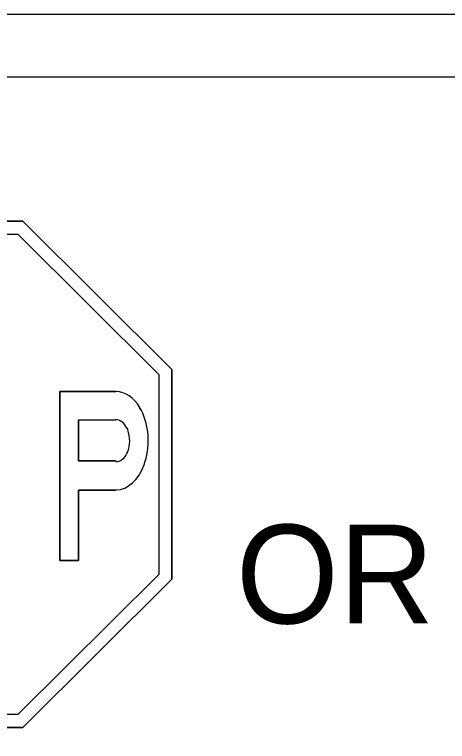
# Model space of a CAD drawing. Extents: x 21.7 to 29.1, y 5.9 to 16.2.
# Drawn here: x 28.039 to 28.39, y 13.558 to 14.147 of the extents above; entities that cross this region are included whole.
import ezdxf

# ---------------------------------------------------------------- set-up
doc = ezdxf.new("R2010")
doc.units = 0
for name, color, linetype in [('DETL-LINE', 7, 'Continuous'), ('DETL-NOTE', 7, 'Continuous'), ('USER-BORD', 7, 'Continuous')]:
    doc.layers.add(name, color=color, linetype=linetype)

msp = doc.modelspace()

# ---------------------------------------------------------------- linework, layer by layer
at = {"layer": 'DETL-LINE'}
for p, q in [((28.04574, 13.97933), (27.87647, 13.97933)), ((28.16646, 13.85926), (28.04574, 13.97933)), ((27.88041, 13.96883), (28.04181, 13.96883)), ((28.04181, 13.96883), (28.15597, 13.85532)), ((28.16646, 13.68933), (28.16646, 13.85926)), ((28.15597, 13.85532), (28.15597, 13.69327)), ((28.09101, 13.84155), (28.07592, 13.84155)), ((28.07592, 13.84155), (28.07592, 13.70442)), ((28.12119, 13.84155), (28.09101, 13.84155)), ((28.14088, 13.82711), (28.14022, 13.82842)), ((28.1418, 13.82612), (28.14116, 13.82727)), ((28.09101, 13.78512), (28.09101, 13.81858)), ((28.09101, 13.81858), (28.12119, 13.81858)), ((28.12119, 13.81858), (28.12147, 13.81861)), ((28.13038, 13.81202), (28.13038, 13.81137)), ((28.13018, 13.81167), (28.1308, 13.81027)), ((28.13038, 13.79186), (28.12948, 13.79008)), ((28.13038, 13.79168), (28.13038, 13.79186)), ((28.14405, 13.78205), (28.14501, 13.78492)), ((28.09101, 13.70442), (28.09101, 13.7615)), ((28.09101, 13.7615), (28.12119, 13.7615)), ((28.07592, 13.70442), (28.09101, 13.70442)), ((28.15597, 13.69327), (28.04181, 13.57976)), ((28.04574, 13.56926), (28.16646, 13.68933)), ((28.04181, 13.57976), (27.88041, 13.57976)), ((27.87647, 13.56926), (28.04574, 13.56926))]:
    msp.add_line(p, q, dxfattribs=at)
for points in [[(28.97321, 14.14685), (25.80407, 14.14685), (25.80407, 13.01694), (28.97321, 13.01694)], [(27.69786, 14.09638), (28.91887, 14.09638), (28.91887, 13.07685), (27.69786, 13.07685)]]:
    msp.add_lwpolyline(points, close=True, dxfattribs=at)
for points in [[(28.12147, 13.84137), (28.12119, 13.84155)], [(28.14022, 13.82842), (28.1405, 13.82843)], [(28.14116, 13.82727), (28.14088, 13.82711)], [(28.13018, 13.81167), (28.13038, 13.81202)], [(28.13038, 13.81137), (28.13018, 13.81167)], [(28.13058, 13.79227), (28.13038, 13.79168)], [(28.12147, 13.78444), (28.12119, 13.78512), (28.09101, 13.78512)], [(28.12119, 13.7615), (28.12147, 13.76168)]]:
    msp.add_lwpolyline(points, dxfattribs=at)
for major_axis, start_param, end_param in [((0, 0.03985), 5.453582, 6.269354), ((0, 0.03985), 4.282505, 5.377627), ((0, 0.01709), 5.347606, 6.250635), ((0, 0.01709), 4.140023, 5.248918), ((0, 0.01709), 3.174143, 3.978532), ((0, 0.03985), 3.155423, 4.201714)]:
    msp.add_ellipse((28.1211, 13.80153), major_axis=major_axis, ratio=0.66, start_param=start_param, end_param=end_param, dxfattribs=at)
at = {"layer": 'USER-BORD'}
for p, q in [((27.87647, 13.97933), (28.04574, 13.97933)), ((28.04574, 13.97933), (28.16646, 13.85926)), ((27.88041, 13.96883), (28.04181, 13.96883)), ((28.04181, 13.96883), (28.15597, 13.85532)), ((28.16646, 13.85926), (28.16646, 13.68933)), ((28.15597, 13.85532), (28.15597, 13.69327)), ((28.07592, 13.70442), (28.07592, 13.84155)), ((28.07592, 13.84155), (28.09101, 13.84155)), ((28.07592, 13.70442), (28.07592, 13.84155)), ((28.07592, 13.84155), (28.09101, 13.84155)), ((28.07592, 13.70442), (28.07592, 13.84155)), ((28.07592, 13.84155), (28.09101, 13.84155)), ((28.12119, 13.84155), (28.09101, 13.84155)), ((28.09101, 13.84155), (28.12119, 13.84155)), ((28.14022, 13.82842), (28.14088, 13.82711)), ((28.09101, 13.81858), (28.09101, 13.78512)), ((28.09101, 13.81858), (28.12119, 13.81858)), ((28.09101, 13.81858), (28.12119, 13.81858)), ((28.09101, 13.78512), (28.09101, 13.81858)), ((28.13038, 13.81137), (28.13038, 13.81202)), ((28.13038, 13.79168), (28.13038, 13.79234)), ((28.09101, 13.78512), (28.12119, 13.78512)), ((28.12119, 13.78512), (28.09101, 13.78512)), ((28.09101, 13.7615), (28.09101, 13.70442)), ((28.12119, 13.7615), (28.09101, 13.7615)), ((28.12119, 13.7615), (28.09101, 13.7615)), ((28.09101, 13.7615), (28.09101, 13.70442)), ((28.09101, 13.70442), (28.07592, 13.70442)), ((28.09101, 13.70442), (28.07592, 13.70442)), ((28.09101, 13.70442), (28.07592, 13.70442)), ((28.15597, 13.69327), (28.04181, 13.57976)), ((28.16646, 13.68933), (28.04574, 13.56926)), ((28.04181, 13.57976), (27.88041, 13.57976)), ((28.04574, 13.56926), (27.87647, 13.56926))]:
    msp.add_line(p, q, dxfattribs=at)
for major_axis, start_param, end_param in [((0, 0.03985), 5.453582, 6.269354), ((0, 0.03985), 5.453582, 6.269354), ((0, 0.03985), 4.282505, 5.377627), ((0, 0.03985), 4.282505, 5.377627), ((0, 0.01709), 5.347606, 6.250635), ((0, 0.01709), 5.347606, 6.250635), ((0, 0.01709), 4.140023, 5.248918), ((0, 0.01709), 4.140023, 5.248918), ((0, 0.01709), 3.174143, 3.978532), ((0, 0.01709), 3.174143, 3.978532), ((0, 0.03985), 3.155423, 4.201714), ((0, 0.03985), 3.155423, 4.201714)]:
    msp.add_ellipse((28.1211, 13.80153), major_axis=major_axis, ratio=0.66, start_param=start_param, end_param=end_param, dxfattribs=at)

# ---------------------------------------------------------------- texts
at = {"layer": 'DETL-NOTE'}
msp.add_text('OR', height=0.08, dxfattribs=at).set_placement((28.21841, 13.65347))

doc.saveas('drawing.dxf')
